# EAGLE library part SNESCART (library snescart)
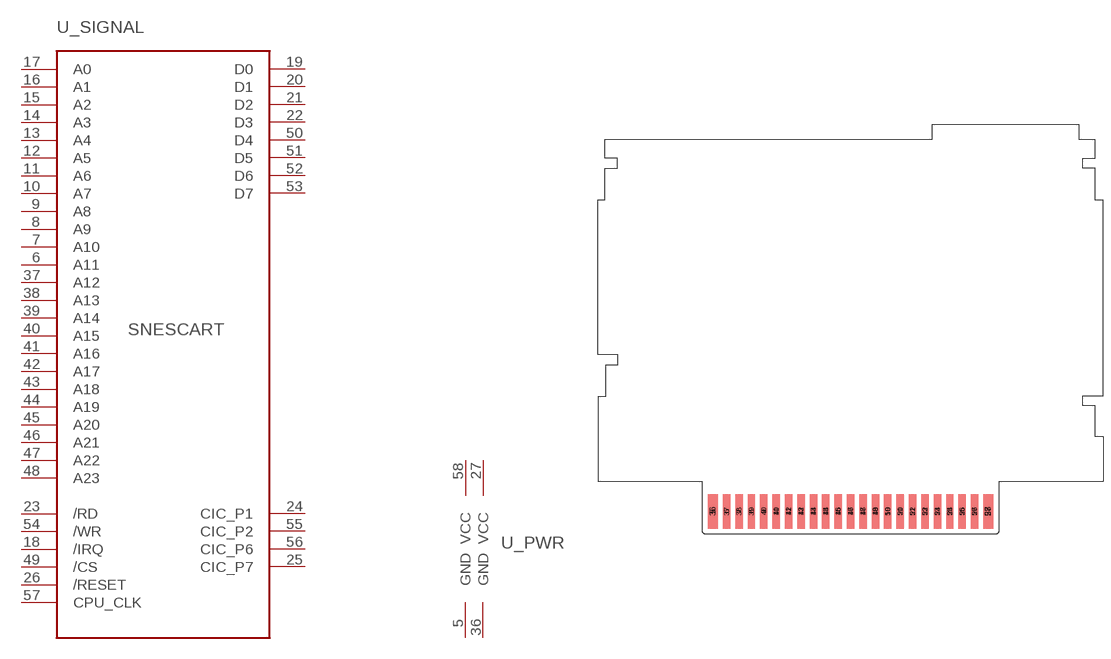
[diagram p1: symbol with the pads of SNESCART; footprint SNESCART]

Designator prefix -; gates _SIGNAL=SNESCART _PWR=CART_PWR

## SNESCART  [SNESCART]
5  _PWR:GND  pwr
6  _SIGNAL:A11
7  _SIGNAL:A10
8  _SIGNAL:A9
9  _SIGNAL:A8
10  _SIGNAL:A7
11  _SIGNAL:A6
12  _SIGNAL:A5
13  _SIGNAL:A4
14  _SIGNAL:A3
15  _SIGNAL:A2
16  _SIGNAL:A1
17  _SIGNAL:A0
18  _SIGNAL:/IRQ
19  _SIGNAL:D0
20  _SIGNAL:D1
21  _SIGNAL:D2
22  _SIGNAL:D3
23  _SIGNAL:/RD
24  _SIGNAL:CIC_P1
25  _SIGNAL:CIC_P7
26  _SIGNAL:/RESET
27  _PWR:VCC  pwr
36  _PWR:GND  pwr
37  _SIGNAL:A12
38  _SIGNAL:A13
39  _SIGNAL:A14
40  _SIGNAL:A15
41  _SIGNAL:A16
42  _SIGNAL:A17
43  _SIGNAL:A18
44  _SIGNAL:A19
45  _SIGNAL:A20
46  _SIGNAL:A21
47  _SIGNAL:A22
48  _SIGNAL:A23
49  _SIGNAL:/CS
50  _SIGNAL:D4
51  _SIGNAL:D5
52  _SIGNAL:D6
53  _SIGNAL:D7
54  _SIGNAL:/WR
55  _SIGNAL:CIC_P2
56  _SIGNAL:CIC_P6
57  _SIGNAL:CPU_CLK
58  _PWR:VCC  pwr

## Footprint SNESCART (pad centres in mm)
smd 2 x 7: 5 -27.75,-0.5; 27 27.75,-0.5
smd 1.5 x 7: 6 -25,-0.5; 7 -22.5,-0.5; 8 -20,-0.5; 9 -17.5,-0.5; 10 -15,-0.5; 11 -12.5,-0.5; 12 -10,-0.5; 13 -7.5,-0.5; 14 -5,-0.5; 15 -2.5,-0.5; 16 0,-0.5; 17 2.5,-0.5; 18 5,-0.5; 19 7.5,-0.5; 20 10,-0.5; 21 12.5,-0.5; 22 15,-0.5; 23 17.5,-0.5; 24 20,-0.5; 25 22.5,-0.5; 26 25,-0.5
smd 2 x 7 bottom: 36 -27.75,-0.5; 58 27.75,-0.5
smd 1.5 x 7 bottom: 37 -25,-0.5; 38 -22.5,-0.5; 39 -20,-0.5; 40 -17.5,-0.5; 41 -15,-0.5; 42 -12.5,-0.5; 43 -10,-0.5; 44 -7.5,-0.5; 45 -5,-0.5; 46 -2.5,-0.5; 47 0,-0.5; 48 2.5,-0.5; 49 5,-0.5; 50 7.5,-0.5; 51 10,-0.5; 52 12.5,-0.5; 53 15,-0.5; 54 17.5,-0.5; 55 20,-0.5; 56 22.5,-0.5; 57 25,-0.5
